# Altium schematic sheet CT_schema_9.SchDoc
size 391 x 238 mm
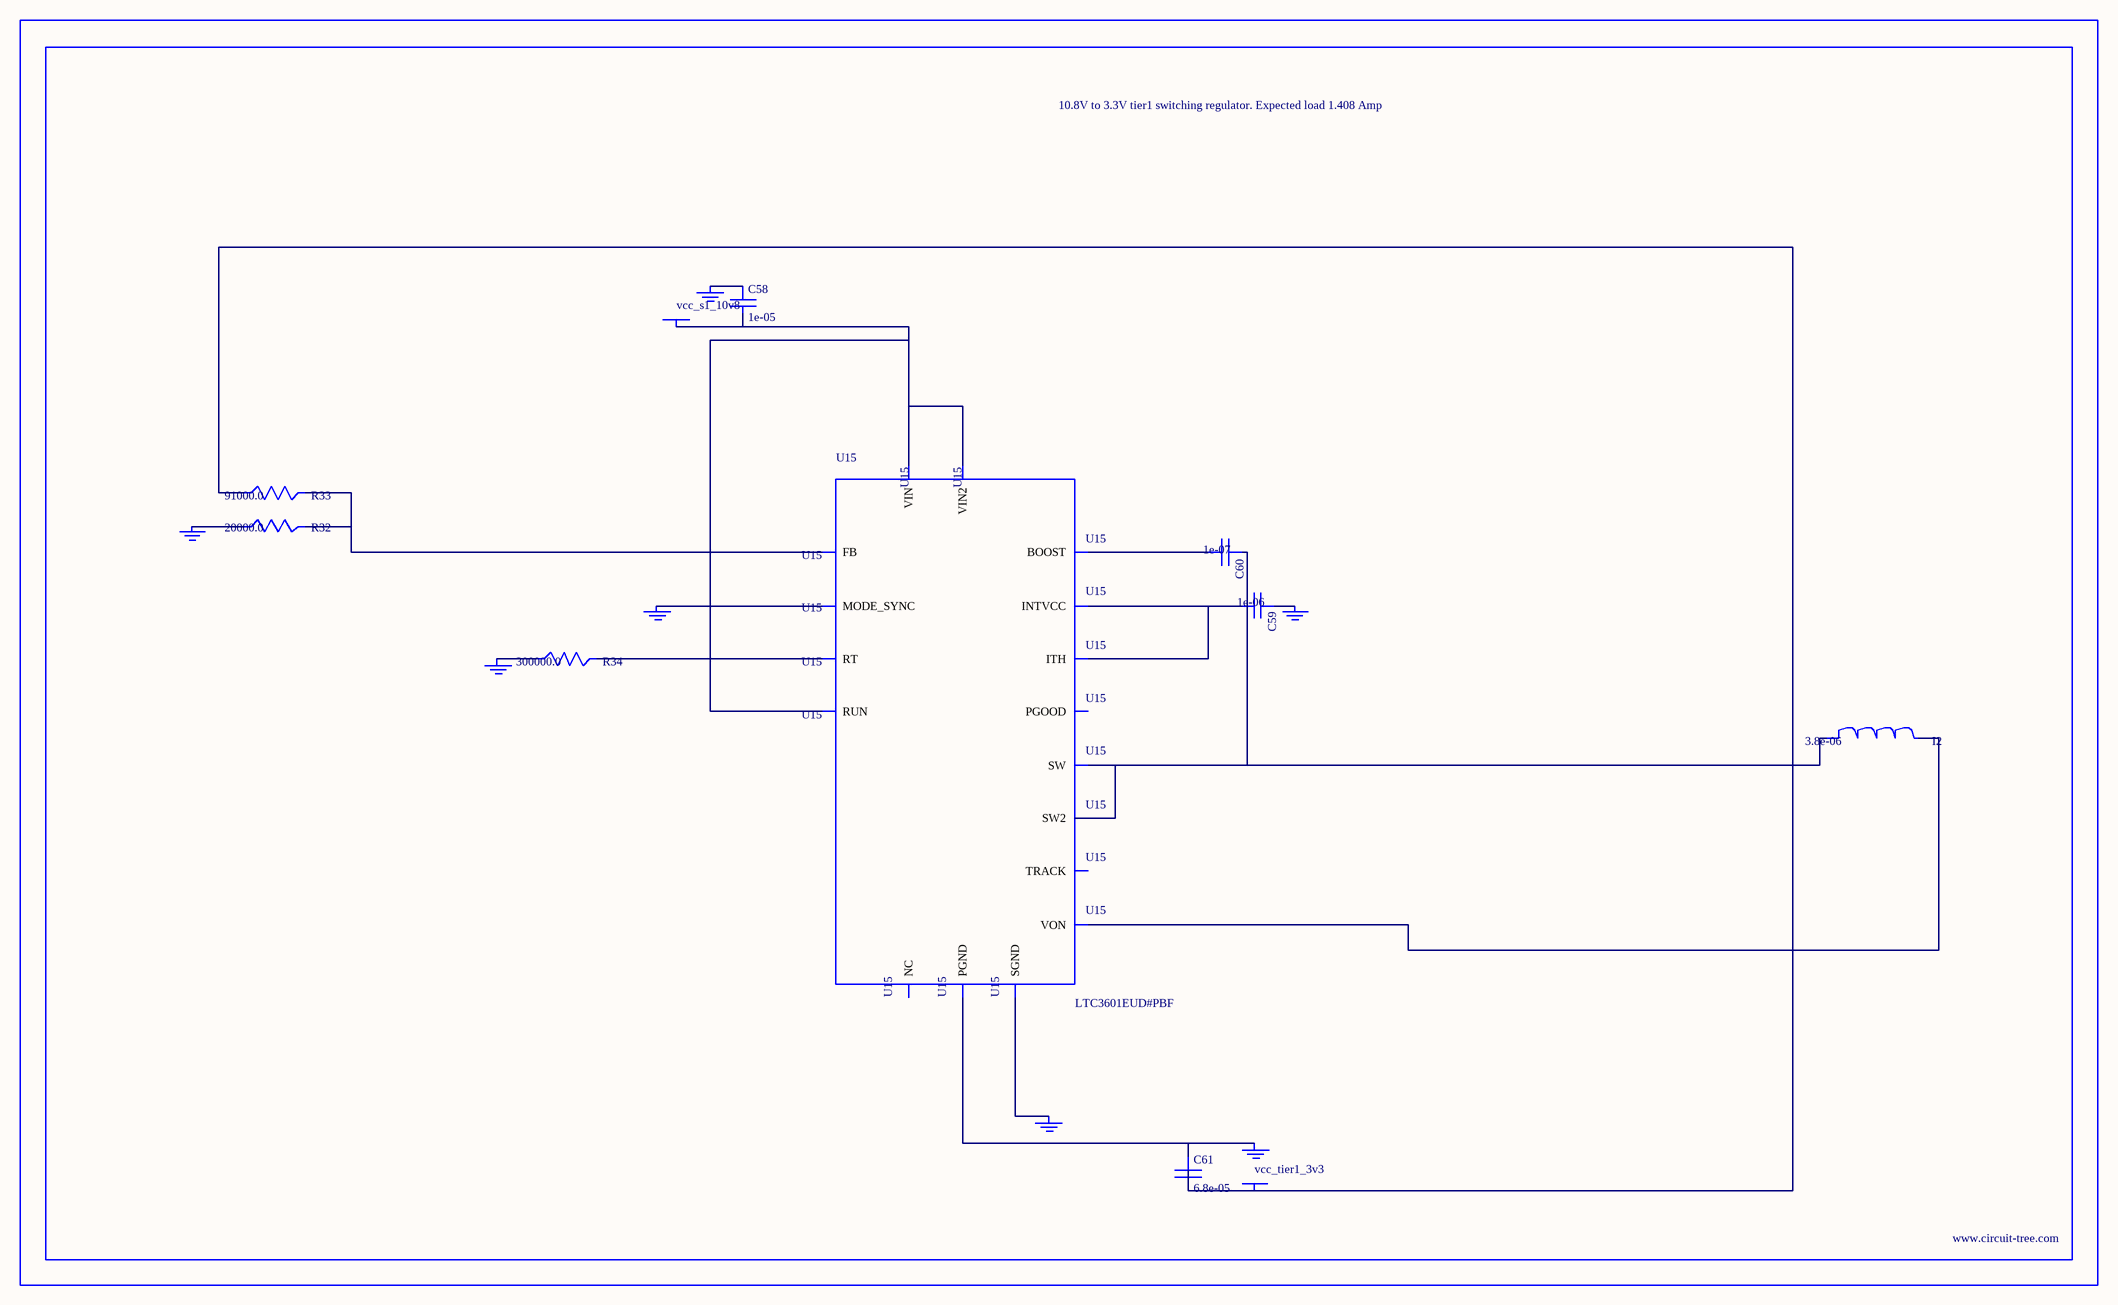
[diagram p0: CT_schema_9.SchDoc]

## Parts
BORDER8  (no value)
C58  1e-05  [C0805]
C59  1e-06  [C0603]
C60  1e-07  [C0402]
C61  6.8e-05  [2220]
GND_INSTANCE_8_0  (no value)
GND_INSTANCE_8_1  (no value)
GND_INSTANCE_8_2  (no value)
GND_INSTANCE_8_3  (no value)
GND_INSTANCE_8_4  (no value)
GND_INSTANCE_8_5  (no value)
GND_INSTANCE_8_6  (no value)
I2  3.8e-06  [DR1040]
POWER_INSTANCE_8_0  vcc_s1_10v8
POWER_INSTANCE_8_1  vcc_tier1_3v3
R32  20000.0  [R0603]
R33  91000.0  [R0603]
R34  300000.0  [R0603]
U15  LTC3601EUD#PBF  [QFN-16_EP]

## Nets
NetC58_1: C58.1 GND_INSTANCE_8_5.0(GND)
NetC58_2: C58.2 POWER_INSTANCE_8_0.0(PWR) U15.14(RUN) U15.15(VIN) U15.16(VIN2)
NetC59_1: C59.1 GND_INSTANCE_8_1.0(GND)
NetC59_2: C59.2 U15.7(INTVCC) U15.12(ITH)
NetC60_1: C60.1 I2.1 U15.3(SW) U15.4(SW2)
NetC60_2: C60.2 U15.6(BOOST)
NetC61_1: C61.1 GND_INSTANCE_8_6.0(GND) U15.17(PGND)
NetC61_2: C61.2 I2.2 POWER_INSTANCE_8_1.0(PWR) R33.1 U15.8(VON)
NetGND_INSTANCE_8_0_0: GND_INSTANCE_8_0.0(GND) U15.1(MODE_SYNC)
NetGND_INSTANCE_8_2_0: GND_INSTANCE_8_2.0(GND) U15.9(SGND)
NetGND_INSTANCE_8_3_0: GND_INSTANCE_8_3.0(GND) R34.1
NetGND_INSTANCE_8_4_0: GND_INSTANCE_8_4.0(GND) R32.1
NetR32_2: R32.2 R33.2 U15.11(FB)
NetR34_2: R34.2 U15.10(RT)

Not connected (* = marked no-connect by the designer): U15 2(PGOOD) 5(NC) 13(TRACK)

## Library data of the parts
BORDER8 = BORDER_PAGE8
C58 = C0805C106K8RACTU
C59 = C0603C105K3RACTU
C60 = C0402C104K3RACTU
C61 = C5750X5R1A686M
GND_INSTANCE_8_0-GND_INSTANCE_8_6 = GND
I2 = DR1040-3R8-R
POWER_INSTANCE_8_0 POWER_INSTANCE_8_1 = PWR
R32 = RC0603JR-0720KL
R33 = RC0603JR-0791KL
R34 = RC0603JR-07300KL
